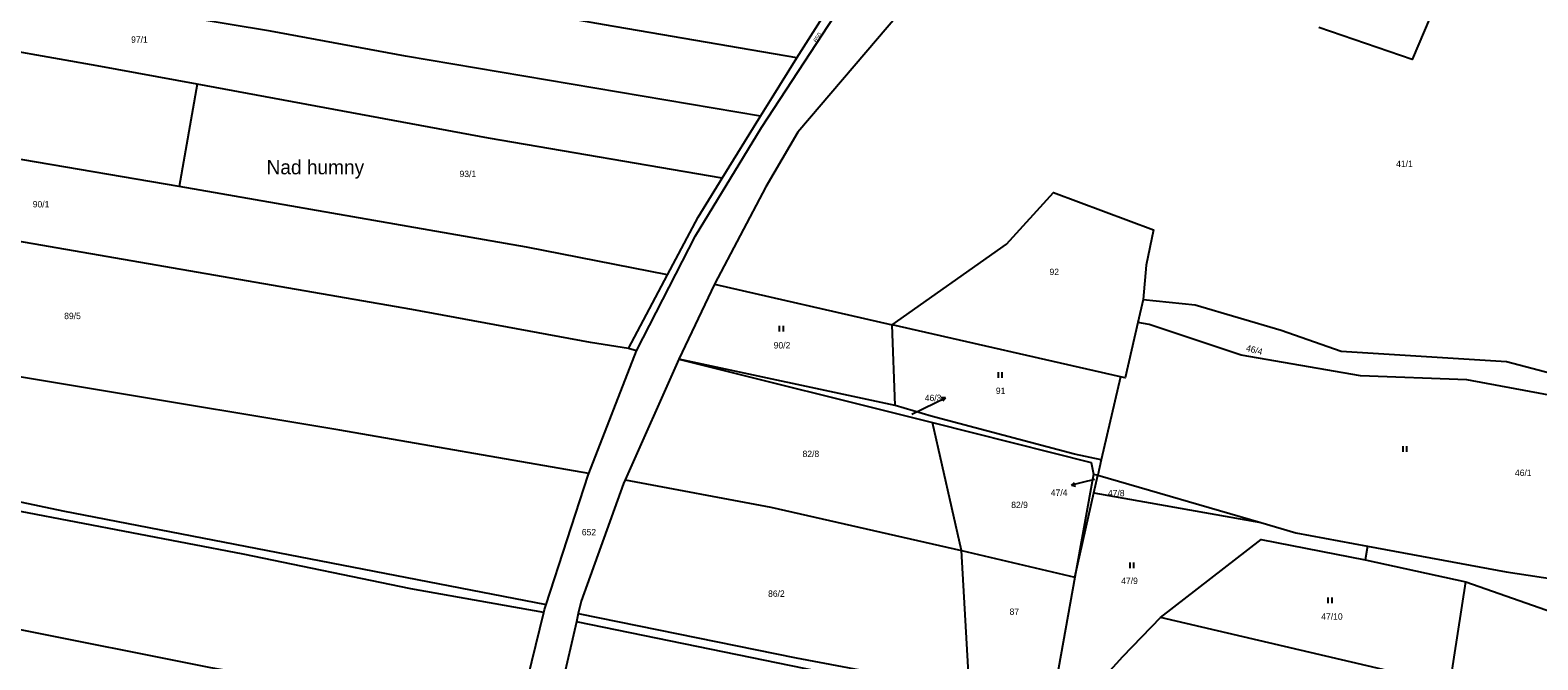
# Model space of a CAD drawing. Extents: x -744566 to -741843, y -1128407 to -1126744.
# Drawn here: x -743441.6 to -743040.3, y -1127345.9 to -1127178.3 of the extents above; entities that cross this region are included whole.
import ezdxf

# ---------------------------------------------------------------- set-up
doc = ezdxf.new("R2010")
doc.units = 0
for name, color, linetype in [('Hranice parcel', 7, 'Continuous'), ('Parcelní čísla', 7, 'Continuous'), ('Pop  PČ popisy', 7, 'Continuous'), ('Značky kultur', 7, 'Continuous')]:
    doc.layers.add(name, color=color, linetype=linetype)

msp = doc.modelspace()

# ---------------------------------------------------------------- linework, layer by layer
at = {"layer": 'Hranice parcel'}
for p, q in [((-743237.55, -1127185.73), (-743227.63, -1127169.97)), ((-743397.19, -1127192.74), (-743402, -1127219.97)), ((-743257.45, -1127217.75), (-743247.25, -1127201.23)), ((-743282.34, -1127263.07), (-743271.94, -1127243.4)), ((-743259.48, -1127245.93), (-743268.91, -1127265.85)), ((-743259.48, -1127245.93), (-743212.13, -1127256.74)), ((-743145.38, -1127250.03), (-743146.77, -1127256.08)), ((-743211.37, -1127278.18), (-743212.13, -1127256.74)), ((-743151.39, -1127270.6), (-743212.13, -1127256.74)), ((-743292.92, -1127296.34), (-743280.26, -1127263.68)), ((-743280.26, -1127263.68), (-743282.34, -1127263.07)), ((-743268.91, -1127265.85), (-743283.26, -1127298.02)), ((-743211.37, -1127278.18), (-743268.91, -1127265.85)), ((-743268.91, -1127265.85), (-743201.41, -1127282.77)), ((-743151.39, -1127270.6), (-743156.49, -1127292.65)), ((-743193.71, -1127316.81), (-743201.41, -1127282.77)), ((-743156.49, -1127292.65), (-743157.42, -1127296.78)), ((-743158.58, -1127296.44), (-743163.52, -1127323.93)), ((-743158.58, -1127296.44), (-743157.42, -1127296.78)), ((-743158.46, -1127301.41), (-743157.42, -1127296.78)), ((-743157.42, -1127296.78), (-743113.98, -1127309.38)), ((-743163.52, -1127323.93), (-743158.46, -1127301.41)), ((-743158.46, -1127301.41), (-743113.98, -1127309.38)), ((-743085.6, -1127315.62), (-743086.21, -1127319.28)), ((-743193.71, -1127316.81), (-743163.52, -1127323.93)), ((-743086.21, -1127319.28), (-743059.46, -1127325.17)), ((-743163.52, -1127323.93), (-743169.65, -1127358.07)), ((-743063.68, -1127352.59), (-743059.46, -1127325.17)), ((-743312.01, -1127362.15), (-743304.91, -1127333.26)), ((-743295.73, -1127333.53), (-743296.23, -1127335.74)), ((-743063.68, -1127352.59), (-743140.7, -1127334.62))]:
    msp.add_line(p, q, dxfattribs=at)
for points in [[(-743280.26, -1127263.68), (-743264.54, -1127233.06), (-743246.95, -1127204.21), (-743235.54, -1127186.77), (-743205.03, -1127140.21), (-743183.34, -1127102.57)], [(-743237.55, -1127185.73), (-743288.76, -1127176.89), (-743377.84, -1127161.22), (-743451.69, -1127150.21), (-743484.81, -1127143.57), (-743511.45, -1127136.91), (-743530.98, -1127131.21), (-743549.04, -1127122.29)], [(-743048.8, -1127120.46), (-743061.12, -1127156.38), (-743073.7, -1127186.12), (-743098.58, -1127177.58)], [(-743247.25, -1127201.23), (-743341.69, -1127185.22), (-743377.67, -1127178.61), (-743471.09, -1127163.04), (-743495.31, -1127157.9), (-743521.74, -1127151.29), (-743534.96, -1127147.61), (-743558.76, -1127136.98)], [(-743195.51, -1127141.13), (-743196.63, -1127142.85), (-743203.92, -1127154.43), (-743215.95, -1127172.74), (-743210.36, -1127174.02), (-743237.28, -1127205.49), (-743245.75, -1127220.06), (-743259.48, -1127245.93)], [(-743397.19, -1127192.74), (-743423.8, -1127187.83), (-743496.12, -1127175.06), (-743525.94, -1127167.89), (-743542.08, -1127162.94), (-743567.27, -1127149.84)], [(-743402, -1127219.97), (-743485.26, -1127205.7), (-743534.64, -1127194.81), (-743556, -1127188.55), (-743584.02, -1127175.2)], [(-743247.25, -1127201.23), (-743244.15, -1127196.22), (-743237.55, -1127185.73)], [(-743282.34, -1127263.07), (-743292.44, -1127261.41), (-743340.01, -1127252.63), (-743486.97, -1127227.24), (-743525.49, -1127217.7), (-743548.02, -1127210.66), (-743568.07, -1127202.32), (-743593.92, -1127190.2)], [(-743257.45, -1127217.75), (-743319.64, -1127207.06), (-743397.19, -1127192.74)], [(-743292.92, -1127296.34), (-743359.24, -1127284.78), (-743489.36, -1127263.15), (-743542.82, -1127249.21), (-743559.61, -1127242.69), (-743582.27, -1127231.48), (-743610.18, -1127214.83)], [(-743271.94, -1127243.4), (-743309.52, -1127236.1), (-743402, -1127219.97)], [(-743271.94, -1127243.4), (-743263.84, -1127228.1), (-743257.45, -1127217.75)], [(-743212.13, -1127256.74), (-743181.72, -1127235.32), (-743169.21, -1127221.57), (-743142.61, -1127231.48), (-743144.55, -1127240.89), (-743145.38, -1127250.03)], [(-743628.48, -1127242.82), (-743587.96, -1127265.17), (-743564.92, -1127275.2), (-743548.91, -1127280.9), (-743494.35, -1127293.28), (-743432.95, -1127306.22), (-743304.3, -1127331.19)], [(-743304.91, -1127333.26), (-743340.32, -1127326.98), (-743384.95, -1127317.8), (-743459.15, -1127303.62), (-743501.66, -1127294.44), (-743555, -1127281.78), (-743584.41, -1127269.73), (-743629.87, -1127244.98)], [(-743145.38, -1127250.03), (-743131.52, -1127251.43), (-743108.65, -1127258.13), (-743092.65, -1127263.72), (-743048.6, -1127266.53), (-743009.87, -1127276.7), (-742990.61, -1127278.9), (-742978.14, -1127278.38)], [(-743146.77, -1127256.08), (-743150.16, -1127270.88), (-743151.39, -1127270.6)], [(-742969.89, -1127289.73), (-742969.99, -1127290.93), (-743008.17, -1127280.91), (-743059.17, -1127271.35), (-743087.47, -1127270.29), (-743119.25, -1127264.8), (-743143.75, -1127256.66), (-743146.77, -1127256.08)], [(-743312.01, -1127362.15), (-743393.56, -1127348.06), (-743446.91, -1127337.38), (-743506.37, -1127328.2), (-743565.99, -1127315.69), (-743593.43, -1127306.05), (-743622.26, -1127292.92), (-743649.24, -1127274.28)], [(-743156.49, -1127292.65), (-743163.66, -1127291.17), (-743201.78, -1127281.02), (-743211.37, -1127278.18)], [(-743201.41, -1127282.77), (-743159.21, -1127293.35), (-743158.58, -1127296.44)], [(-743304.3, -1127331.19), (-743293.07, -1127296.72), (-743292.92, -1127296.34)], [(-743283.26, -1127298.02), (-743283.68, -1127298.96), (-743294.99, -1127330.28), (-743295.73, -1127333.53)], [(-743283.26, -1127298.02), (-743244.44, -1127305.3), (-743193.71, -1127316.81)], [(-743113.98, -1127309.38), (-743104.71, -1127312.07), (-743085.6, -1127315.62)], [(-743140.7, -1127334.62), (-743113.92, -1127313.85), (-743086.21, -1127319.28)], [(-743085.6, -1127315.62), (-743048.7, -1127322.46), (-743017.08, -1127327.24), (-743009.69, -1127326.1)], [(-743295.73, -1127333.53), (-743237.76, -1127345.4), (-743191.59, -1127354.07), (-743193.71, -1127316.81)], [(-743059.46, -1127325.17), (-743032.86, -1127334.46), (-743014.16, -1127339.69)], [(-743304.91, -1127333.26), (-743304.73, -1127332.52), (-743304.3, -1127331.19)], [(-743296.23, -1127335.74), (-743299.98, -1127352.31), (-743302.98, -1127364.26)], [(-743170.53, -1127362.98), (-743196.16, -1127356.25), (-743296.23, -1127335.74)], [(-743140.7, -1127334.62), (-743150.85, -1127345.11), (-743161.95, -1127357.36)]]:
    msp.add_lwpolyline(points, dxfattribs=at)
at = {"layer": 'Pop  PČ popisy'}
for p, q in [((-743200.69, -1127277.5), (-743197.993, -1127276.184)), ((-743197.993, -1127276.184), (-743199.112, -1127276.173)), ((-743197.993, -1127276.184), (-743198.673, -1127277.074)), ((-743206.97, -1127280.56), (-743200.69, -1127277.5)), ((-743164.452, -1127299.416), (-743163.601, -1127298.688)), ((-743161.54, -1127298.69), (-743164.452, -1127299.416)), ((-743164.452, -1127299.416), (-743163.359, -1127299.66)), ((-743158.26, -1127297.86), (-743161.54, -1127298.69))]:
    msp.add_line(p, q, dxfattribs=at)
at = {"layer": 'Značky kultur'}
for p, q in [((-743242.131, -1127258.55), (-743242.131, -1127257.05)), ((-743241.13, -1127258.55), (-743241.13, -1127257.05)), ((-743183.861, -1127270.84), (-743183.861, -1127269.34)), ((-743182.86, -1127270.84), (-743182.86, -1127269.34)), ((-743076.141, -1127290.53), (-743076.141, -1127289.03)), ((-743075.14, -1127290.53), (-743075.14, -1127289.03)), ((-743148.811, -1127321.49), (-743148.811, -1127319.99)), ((-743147.81, -1127321.49), (-743147.81, -1127319.99)), ((-743096.071, -1127330.79), (-743096.071, -1127329.29)), ((-743095.07, -1127330.79), (-743095.07, -1127329.29))]:
    msp.add_line(p, q, dxfattribs=at)

# ---------------------------------------------------------------- texts
at = {"layer": 'Parcelní čísla'}
for s, p in [('97/1', (-743414.76, -1127181.7)), ('93/1', (-743327.33, -1127217.43)), ('41/1', (-743077.99, -1127214.74)), ('90/1', (-743440.95, -1127225.5)), ('92', (-743170.27, -1127243.5)), ('89/5', (-743432.58, -1127255.23)), ('90/2', (-743243.7, -1127263.04)), ('46/3', (-743203.472, -1127277.04)), ('91', (-743184.56, -1127275.15)), ('82/8', (-743236.01, -1127291.93)), ('46/1', (-743046.37, -1127296.96)), ('82/9', (-743180.47, -1127305.5)), ('47/4', (-743169.932, -1127302.263)), ('47/8', (-743154.72, -1127302.37)), ('652', (-743294.774, -1127312.77)), ('47/9', (-743151.19, -1127325.7)), ('86/2', (-743245.19, -1127329.13)), ('87', (-743180.9, -1127333.94)), ('47/10', (-743097.93, -1127335.2))]:
    msp.add_text(s, height=1.7, dxfattribs=at).set_placement(p)
for s, height, rotation, p in [('650', 1.19, 56, (-743232.289, -1127181.758)), ('46/4', 1.7, 345, (-743118.099, -1127263.641))]:
    msp.add_text(s, height=height, rotation=rotation, dxfattribs=at).set_placement(p)
at = {"layer": 'Pop  PČ popisy'}
msp.add_text('Nad humny', height=3.8, dxfattribs=at).set_placement((-743378.71, -1127216.69))

doc.saveas('drawing.dxf')
